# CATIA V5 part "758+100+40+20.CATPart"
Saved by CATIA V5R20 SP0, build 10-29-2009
Part number: 758+100+40+20
Revision: TUTTO
Definition: NON CONOSCIUTO
Nomenclature: 758+100+40+20
Source: Unknown
Bounding box of the stored display mesh (mm): x -50 to 50, y 0 to 40, z -50 to 50
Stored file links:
  C:\Users\Utente\Desktop\IO LAVORO\3D X SITO CF\X 3D SITO CF 27-09-2020\758\758+100+40+20.CATPart
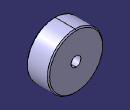
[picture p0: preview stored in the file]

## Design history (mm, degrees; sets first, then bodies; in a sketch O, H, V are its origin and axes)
Body1 "Smusso 2x45°" (main body)
  Solid1: solid without history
